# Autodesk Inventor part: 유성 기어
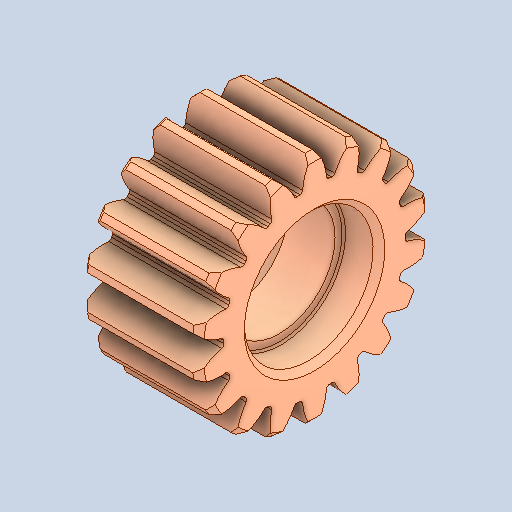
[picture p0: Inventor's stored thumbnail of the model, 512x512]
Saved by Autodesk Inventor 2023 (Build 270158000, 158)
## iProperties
Created: 2026-04
Part Number: 유성 기어
Material: 강철, 합금
Document SubType Name: Modeling
Designer: home
Density: 7.73 g/cm^3
Appearance: 기본값
Author: jhkim
Sending System: Autodesk Inventor 2027
Preprocessor: ST-DEVELOPER v20.1
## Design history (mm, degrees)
feature "솔리드1"
node "솔리드2"
